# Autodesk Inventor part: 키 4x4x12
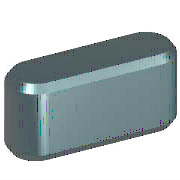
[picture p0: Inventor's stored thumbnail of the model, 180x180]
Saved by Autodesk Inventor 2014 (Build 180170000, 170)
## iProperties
IsCustomPart: 1
Created: 2012-02
Part Number: 키 4x4x12
Material: 강철, 연강
Description: 키 및 해당 키홈
Document SubType Name: Modeling
Standard: KS B 1311
Designer: mduedu
Standards Organization: KS
Language: ko-KR
Size Designation: 4 x 4 x 12
Categories: <MemberInstance><Categories><Category DisplayName="샤프트 부품" InternalName="7f7aeb1f-a693-4053-b835-cee3144e0d98" Mnemonic="SHFT"><Category DisplayName="키" Interna
Density: 7.86 g/cm^3
Appearance: 노란색
Mass: 1.38739 g
Surface Area: 1.94869 cm^2
Volume: 0.176513 cm^3
Author: mduedu
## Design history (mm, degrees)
workplane "Work Plane1"
workplane "Work Plane2"
sketch "스케치1"
  geometry: L1 (2, 2)-(10, 2); L2 (10, -2)-(2, -2); L3 (0, 9.4)-(0, -7.4) reference; L4 (-5, 0)-(30, 0) reference; L5 (12, 0)-(12, 7); A1 r 2 centre (2, 0) between (2, 2) and (2, -2); A2 r 2 centre (10, 0) between (10, -2) and (10, 2)
  constraints: 6 end point, 5 point on circle, 4 tangent, 3 point on line, 2 centre point, 1 horizontal, 1 parallel, 1 perpendicular
  dimensions: "d0" = 2 radius of A1 (= 0.5 x PB); "d13" = 2 radius of A2 (= 0.5 x PB); "d14" = 12 distance between parallel lines of L5 L3 (= NLG)
extrude "본체1" new body sketch "스케치1" taper "d3" = 0 deg; stored distance "d4" = 10
workplane "Work Plane3"
body "Solid1"
chamfer "모따기1" distance "d8" = 0.25 (= PHH); stored, may be unused: second distance "d9" = 0.25 (= PHH), angle "d15" = 45 deg
other parameters: "d1" = -2.5 (= -PNT), "d2" = 1.5 (= PH - PNT), "NLG" = 12 [user parameter; used in 3 equation terms], "PB" = 4 [user parameter; used in 2 equation terms], "PNT" = 2.5 [user parameter; used in 2 equation terms], "PH" = 4 [user parameter; used in 1 equation term], "PHH" = 0.25 [user parameter; used in 2 equation terms], "d10" = 0, "d16" = 0, "d17" = 0, "d18" = 0, "PLB2" = 12 (= NLG) [user parameter], "WDMAX" = 12 [user parameter], "PLB1" = 12 (= NLG) [user parameter], "RR" = 0.08 [user parameter], "PUEB" = 1.8 [user parameter]
